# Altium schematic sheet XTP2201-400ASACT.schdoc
size 127 x 101 mm
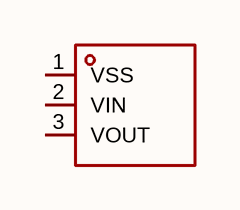
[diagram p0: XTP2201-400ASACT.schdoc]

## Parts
Q?  xtp2201-400asact  [SOT-89-3_L4.3-W2.3-P1.50-LS4.3-BR]  (value not drawn)

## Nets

Not connected (* = marked no-connect by the designer): Q? 1(VSS) 2(VIN) 3(VOUT)

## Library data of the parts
Q? = xtp2201-400asact: 输出极性:正极;工作电压:18V;输出电压:4V;输出电流:500mA;电源纹波抑制比(PSRR):76dB@(100Hz);输出类型:固定;; Manufacturer: XTX(芯天下); AddInBom: yes; ModelId: 13a61ebef0f84f538eafb98eafc62ef6; ModelTransform: 161.22,177.165,0,0,0,0,-13.11,0,0; Output Configuration: 正极; Voltage - Supply: 18V; Output Voltage: 4V; Output Current: 500mA; Voltage Dropout: 135mV@(100mA); standby current: 1.8uA; Output Type: 固定; Number of Outputs: 1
